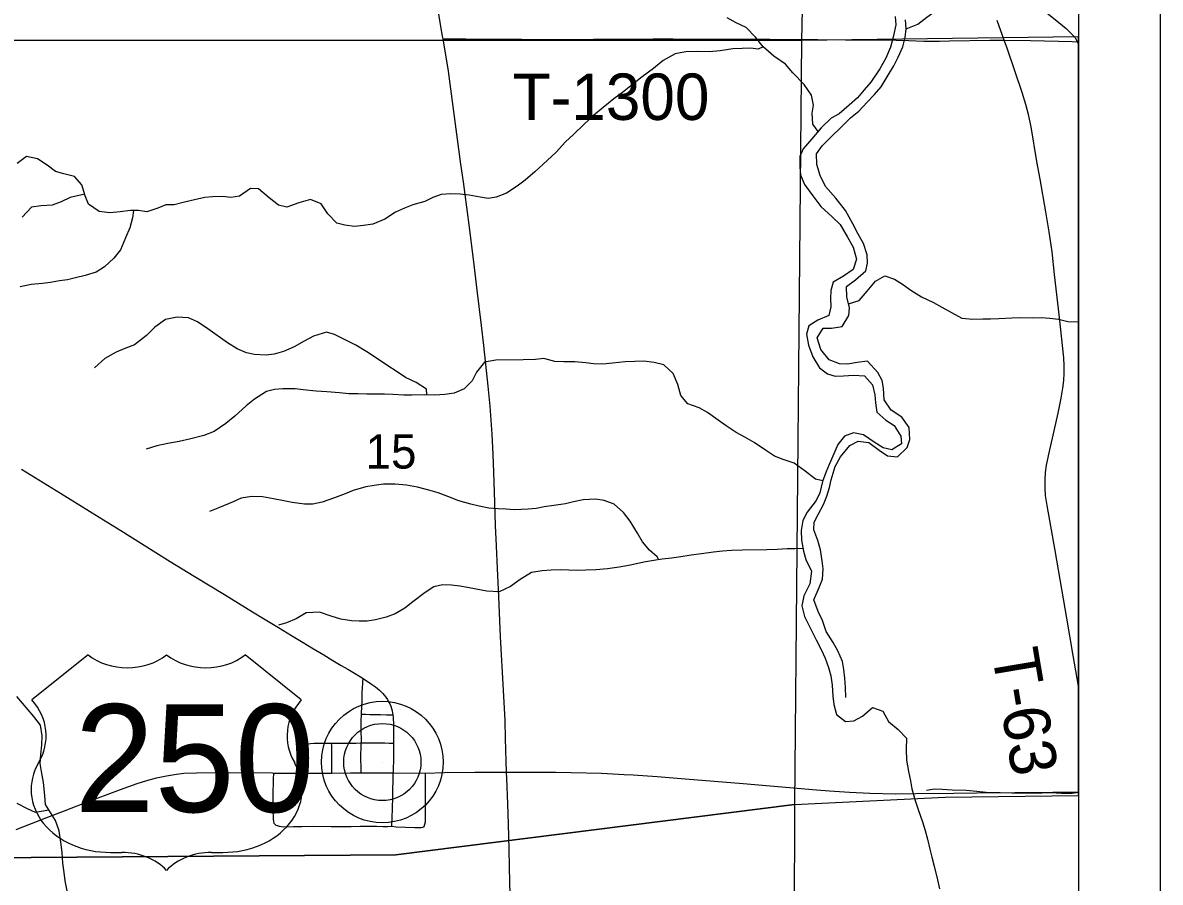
# Model space of a CAD drawing. Extents: x 0 to 34, y 0 to 22.
# Drawn here: x 14.616 to 16.008, y 10.238 to 11.289 of the extents above; entities that cross this region are included whole.
import ezdxf

# ---------------------------------------------------------------- set-up
doc = ezdxf.new("R2010")
doc.units = 0
for name, color, linetype in [('Default', 7, 'Continuous'), ('GM_X_County_Road', 7, 'Continuous'), ('GM_X_Major_River', 7, 'Continuous'), ('GM_X_Minor_River', 7, 'Continuous'), ('GM_X_Section', 7, 'Continuous'), ('GM_X_Section_Text', 7, 'Continuous'), ('GM_X_Township_Road', 7, 'Continuous'), ('GM_X_Township_Road_Text', 7, 'Continuous'), ('GM_X_Unincorporated', 7, 'Continuous'), ('GM_X_Unincorporated_Location', 7, 'Continuous'), ('GM_X_US_Location', 7, 'Continuous'), ('GM_X_US_Route', 7, 'Continuous'), ('GM_X_US_Shield', 7, 'Continuous'), ('SH_Data', 7, 'Continuous')]:
    doc.layers.add(name, color=color, linetype=linetype)

msp = doc.modelspace()

# ---------------------------------------------------------------- linework, layer by layer
at = {"layer": 'Default'}
msp.add_lwpolyline([(15.9079, 10.3439), (15.9079, 11.2722), (15.569, 11.2675), (15.5602, 10.3325), (15.7447, 10.3415)], close=True, dxfattribs=at)
at = {"layer": 'GM_X_County_Road'}
for points in [[(15.1304, 11.2698), (15.1298, 11.2729), (15.1239, 11.3066)], [(15.208, 10.3722), (15.2076, 10.3857), (15.2069, 10.4136), (15.2061, 10.4354), (15.2041, 10.4726), (15.2007, 10.5377), (15.1984, 10.5873), (15.1969, 10.6215), (15.1956, 10.6494), (15.1944, 10.6742), (15.1935, 10.7021), (15.1923, 10.7394), (15.1915, 10.7611), (15.1902, 10.786), (15.1878, 10.8201), (15.1856, 10.8448), (15.1801, 10.8942), (15.1773, 10.9189), (15.172, 10.9621), (15.1688, 10.9898), (15.1629, 11.0361), (15.1592, 11.0638), (15.1551, 11.0946), (15.1521, 11.1161), (15.1472, 11.153), (15.1427, 11.1869), (15.1368, 11.23), (15.1304, 11.2698)], [(14.6144, 10.7431), (14.6356, 10.7301), (14.662, 10.7138), (14.6858, 10.6991), (14.7096, 10.6844), (14.7359, 10.668), (14.7754, 10.6431), (14.7965, 10.63), (14.8256, 10.6121), (14.8627, 10.5895), (14.8972, 10.5685), (14.9105, 10.5605), (14.9291, 10.5493), (14.9449, 10.5395), (14.9591, 10.5308), (14.9698, 10.5243), (14.9844, 10.5157), (14.9953, 10.5091), (15.0056, 10.5029), (15.0137, 10.4982), (15.0239, 10.4921), (15.0327, 10.4867)], [(15.0327, 10.4867), (15.0428, 10.4799), (15.0476, 10.4765), (15.0524, 10.4725), (15.0566, 10.4685), (15.0602, 10.4642), (15.0622, 10.461), (15.0637, 10.4584), (15.065, 10.4557), (15.0662, 10.4529), (15.0671, 10.4501), (15.0679, 10.4472), (15.0685, 10.4447), (15.0689, 10.4425)], [(15.0689, 10.4425), (15.0694, 10.439), (15.0695, 10.4304), (15.0697, 10.4172), (15.0698, 10.4079)], [(15.0698, 10.4079), (15.0697, 10.3976), (15.0696, 10.3928), (15.0695, 10.3851), (15.0694, 10.3783), (15.0692, 10.3715)], [(15.2124, 10.2213), (15.2116, 10.2561), (15.2111, 10.2779), (15.2103, 10.3087), (15.2097, 10.3336), (15.2083, 10.3646), (15.208, 10.3722)]]:
    msp.add_lwpolyline(points, dxfattribs=at)
at = {"layer": 'GM_X_Major_River'}
for points in [[(15.6837, 11.2969), (15.6845, 11.2867), (15.6811, 11.2719), (15.6778, 11.2594), (15.6721, 11.2461), (15.6646, 11.2328), (15.6536, 11.2168), (15.6457, 11.2073), (15.6374, 11.1974), (15.6271, 11.1883), (15.615, 11.178), (15.6052, 11.1726), (15.5931, 11.1608), (15.5814, 11.1471), (15.5708, 11.135), (15.567, 11.1255), (15.5667, 11.1126), (15.5678, 11.1031), (15.5724, 11.0913), (15.5827, 11.0777), (15.5926, 11.0644), (15.6063, 11.052), (15.6162, 11.0425), (15.625, 11.027), (15.6322, 11.0149), (15.6364, 11.0001), (15.6323, 10.9872), (15.6202, 10.9792), (15.6077, 10.9719), (15.6047, 10.9617), (15.6043, 10.9518), (15.6047, 10.9419), (15.6025, 10.9309), (15.5888, 10.9252), (15.5779, 10.9183), (15.5752, 10.9084), (15.5776, 10.8948), (15.5829, 10.8804), (15.5909, 10.8671), (15.6008, 10.8596), (15.6103, 10.857), (15.6205, 10.8574), (15.6327, 10.8582), (15.6459, 10.8571), (15.6558, 10.8461), (15.6585, 10.834), (15.6593, 10.8241), (15.6609, 10.8127), (15.6723, 10.8029), (15.6822, 10.7965), (15.6905, 10.7836), (15.6913, 10.7741), (15.6796, 10.7669), (15.669, 10.7691), (15.6579, 10.7759), (15.6446, 10.785), (15.6325, 10.7876), (15.6215, 10.7834), (15.6132, 10.7731), (15.6072, 10.759), (15.6026, 10.7488), (15.5985, 10.7389), (15.5947, 10.7279), (15.5914, 10.7142), (15.5868, 10.7047), (15.5759, 10.6903), (15.5706, 10.6804), (15.5687, 10.6679), (15.5691, 10.6561), (15.5715, 10.6428), (15.5741, 10.6326), (15.581, 10.6182), (15.5792, 10.6026), (15.5716, 10.5882), (15.5694, 10.5757), (15.5724, 10.5628), (15.5786, 10.5507), (15.5869, 10.5344), (15.5934, 10.5215), (15.598, 10.5116), (15.6018, 10.5003), (15.6049, 10.49)], [(15.6232, 10.4635), (15.6228, 10.476), (15.622, 10.4874), (15.6208, 10.4977), (15.6189, 10.5075), (15.6135, 10.5208), (15.6078, 10.531), (15.5991, 10.5443), (15.5948, 10.5579), (15.5895, 10.5689), (15.5838, 10.5833), (15.5906, 10.5981), (15.5947, 10.6084), (15.5954, 10.6209), (15.5943, 10.6308), (15.5923, 10.6444), (15.5889, 10.6558), (15.5839, 10.6687), (15.5843, 10.6782), (15.5899, 10.6884), (15.5959, 10.6998), (15.6001, 10.7101), (15.6031, 10.7207), (15.6053, 10.7302), (15.6102, 10.7465), (15.6166, 10.7583), (15.628, 10.772), (15.6382, 10.7774), (15.6511, 10.7755), (15.664, 10.7664), (15.6743, 10.7593), (15.6864, 10.7582), (15.6982, 10.7696), (15.7015, 10.7794), (15.7007, 10.7939), (15.6916, 10.8067), (15.6787, 10.8154), (15.6699, 10.8279), (15.6691, 10.842), (15.6676, 10.8514), (15.6622, 10.8613), (15.6497, 10.8753), (15.6372, 10.8734), (15.6254, 10.8714), (15.6156, 10.8718), (15.6026, 10.8767), (15.5927, 10.8895), (15.5881, 10.9036), (15.5953, 10.9157), (15.6056, 10.9154), (15.6185, 10.9177), (15.6268, 10.931), (15.6275, 10.9405), (15.6244, 10.9538), (15.624, 10.9666), (15.635, 10.9747), (15.6475, 10.9857), (15.6497, 10.9952), (15.6493, 11.0054), (15.6447, 11.0191), (15.6378, 11.0316), (15.6317, 11.0433), (15.6226, 11.0596), (15.6108, 11.0747), (15.5982, 11.0888), (15.5917, 11.1024), (15.5875, 11.116), (15.5871, 11.1289), (15.5943, 11.1388), (15.6056, 11.1502), (15.617, 11.1613), (15.6287, 11.1731), (15.6389, 11.1811), (15.6491, 11.1921), (15.6582, 11.2016), (15.6662, 11.2111), (15.6748, 11.2252), (15.682, 11.2366), (15.6873, 11.2472), (15.6929, 11.2598), (15.6959, 11.2712), (15.6971, 11.2818), (15.6963, 11.2928)], [(15.6049, 10.49), (15.6065, 10.4786), (15.6073, 10.4654), (15.6084, 10.4551), (15.6119, 10.443), (15.6229, 10.4343), (15.6331, 10.4351), (15.6434, 10.4408), (15.6558, 10.4515), (15.6684, 10.447), (15.6752, 10.4341), (15.6874, 10.4246), (15.6973, 10.4137), (15.697, 10.4004), (15.6974, 10.3871), (15.6997, 10.3731), (15.7024, 10.3617), (15.7039, 10.3518), (15.7078, 10.3374), (15.712, 10.3253), (15.7169, 10.3113), (15.7204, 10.301), (15.7231, 10.2904), (15.7261, 10.2779), (15.7285, 10.2684), (15.7311, 10.2574), (15.7354, 10.2404), (15.7377, 10.2294)]]:
    msp.add_lwpolyline(points, dxfattribs=at)
at = {"layer": 'GM_X_Minor_River'}
for points in [[(15.697, 11.2817), (15.7111, 11.2875), (15.7224, 11.2963), (15.7342, 11.3047), (15.7501, 11.3142), (15.7641, 11.3203), (15.7758, 11.3238), (15.7857, 11.3265), (15.7952, 11.3261), (15.8077, 11.3246), (15.8233, 11.3213), (15.8335, 11.3183), (15.8517, 11.3123), (15.8635, 11.3058), (15.8795, 11.2934), (15.8928, 11.2824), (15.9038, 11.2711), (15.9079, 11.2629)], [(15.5892, 11.1563), (15.5828, 11.1653), (15.582, 11.1786), (15.5835, 11.1885), (15.5812, 11.2006), (15.5721, 11.2139), (15.5584, 11.2279), (15.5492, 11.2385), (15.5352, 11.2483), (15.5222, 11.26), (15.5127, 11.2718), (15.5013, 11.2835), (15.4888, 11.2891), (15.4778, 11.2952)], [(15.5222, 11.26), (15.5158, 11.257), (15.5063, 11.2581), (15.4961, 11.258), (15.4847, 11.2573), (15.4695, 11.2549), (15.4559, 11.2538), (15.4415, 11.2541), (15.4274, 11.2537), (15.4142, 11.2513), (15.3998, 11.2433), (15.388, 11.2334), (15.374, 11.2231), (15.3623, 11.2136), (15.3498, 11.2041), (15.3392, 11.1961), (15.3263, 11.1858), (15.3142, 11.1759), (15.3029, 11.1653), (15.29, 11.1527), (15.2802, 11.1436), (15.2685, 11.131), (15.2575, 11.1207), (15.2424, 11.107), (15.2306, 11.0967), (15.2208, 11.0895), (15.2079, 11.0807), (15.1954, 11.0758), (15.1856, 11.0742), (15.1757, 11.0757), (15.1624, 11.0783), (15.1514, 11.0794), (15.14, 11.0801), (15.1279, 11.079), (15.1177, 11.0755), (15.1078, 11.0706), (15.0934, 11.0667), (15.0832, 11.0625), (15.0722, 11.0575), (15.0589, 11.0488), (15.0445, 11.0427), (15.0328, 11.0411), (15.0218, 11.0399), (15.01, 11.0418), (15.0005, 11.0441), (14.9891, 11.0554), (14.9811, 11.0679), (14.9682, 11.0732), (14.9538, 11.0689), (14.939, 11.0636), (14.9291, 11.0662), (14.9174, 11.0749), (14.9044, 11.0859), (14.8946, 11.0866), (14.8813, 11.0771), (14.8707, 11.0755), (14.8608, 11.0766), (14.8483, 11.0762), (14.8388, 11.0754), (14.8263, 11.0727), (14.8138, 11.0697), (14.8013, 11.0666), (14.7911, 11.0666), (14.7812, 11.0624), (14.768, 11.0578), (14.7577, 11.0596), (14.7478, 11.0596), (14.735, 11.058), (14.7224, 11.0569), (14.7095, 11.0583), (14.6966, 11.0674), (14.6924, 11.0776), (14.6882, 11.0909), (14.6791, 11.1011), (14.6662, 11.1045), (14.6559, 11.1075), (14.646, 11.1151), (14.6342, 11.123), (14.6206, 11.1256), (14.6092, 11.1172)], [(14.6919, 11.0794), (14.6738, 11.0753), (14.6628, 11.07), (14.6519, 11.0661), (14.6386, 11.0653), (14.6268, 11.0638), (14.6151, 11.0516)], [(14.7516, 11.0596), (14.7501, 11.0505), (14.7468, 11.0383), (14.7419, 11.0262), (14.7355, 11.0114), (14.7275, 11.0011), (14.7158, 10.9908), (14.7056, 10.9843), (14.6923, 10.9801), (14.6806, 10.9771), (14.6707, 10.9747), (14.6608, 10.9736), (14.6499, 10.9716), (14.64, 10.9701), (14.6263, 10.9689), (14.6127, 10.9662)], [(15.6264, 10.9453), (15.6396, 10.9496), (15.6494, 10.961), (15.6593, 10.9732), (15.671, 10.9797), (15.6828, 10.9756), (15.6926, 10.9695), (15.7025, 10.9623), (15.7158, 10.954), (15.7303, 10.9469), (15.7405, 10.9412), (15.7523, 10.9348), (15.7652, 10.928), (15.7785, 10.9265), (15.7906, 10.9269), (15.8001, 10.927), (15.8104, 10.9274), (15.8263, 10.9282), (15.8358, 10.9286), (15.8513, 10.9283), (15.8623, 10.9287), (15.8726, 10.9279), (15.8832, 10.9265), (15.895, 10.9238), (15.9079, 10.9232)], [(15.1106, 10.8341), (15.11, 10.841), (15.0974, 10.8493), (15.0845, 10.8553), (15.0728, 10.8629), (15.0629, 10.8693), (15.0488, 10.8788), (15.037, 10.8867), (15.0237, 10.8946), (15.0104, 10.9014), (14.9975, 10.9078), (14.9876, 10.9108), (14.9717, 10.9058), (14.9604, 10.8997), (14.9479, 10.8929), (14.935, 10.8871), (14.9236, 10.8837), (14.9138, 10.8825), (14.8997, 10.8832), (14.8898, 10.8855), (14.8785, 10.8904), (14.8667, 10.8976), (14.8423, 10.9149), (14.8298, 10.9232), (14.8188, 10.9281), (14.8051, 10.9292), (14.7907, 10.9262), (14.7775, 10.917), (14.7673, 10.9067), (14.7529, 10.8953), (14.7408, 10.8907), (14.7301, 10.8861), (14.7165, 10.8785), (14.7036, 10.8671)], [(15.5951, 10.7289), (15.586, 10.7309), (15.5734, 10.7404), (15.5598, 10.7502), (15.5465, 10.7547), (15.5358, 10.7588), (15.5248, 10.7664), (15.5111, 10.7755), (15.4994, 10.7822), (15.4891, 10.7879), (15.4766, 10.7962), (15.4671, 10.803), (15.4537, 10.8125), (15.4435, 10.8181), (15.4298, 10.823), (15.4211, 10.8332), (15.4176, 10.8465), (15.4119, 10.8601), (15.4005, 10.8707), (15.3887, 10.8734), (15.3758, 10.8752), (15.3648, 10.8748), (15.353, 10.8744), (15.3375, 10.8728), (15.3257, 10.8716), (15.3144, 10.872), (15.3049, 10.8731), (15.2916, 10.8742), (15.2779, 10.8745), (15.2669, 10.8749), (15.2536, 10.8786), (15.2434, 10.8771), (15.2282, 10.8767), (15.1949, 10.8766), (15.1812, 10.8739), (15.1714, 10.8617), (15.1661, 10.851), (15.1563, 10.8415), (15.1438, 10.8362), (15.1324, 10.8346), (15.1203, 10.8338), (15.1081, 10.8342), (15.0922, 10.8337), (15.0823, 10.8337), (15.0687, 10.8344), (15.0588, 10.8348), (15.0372, 10.8347), (15.0266, 10.8351), (15.0148, 10.8354), (15.0034, 10.8365), (14.9882, 10.8376), (14.975, 10.8387), (14.959, 10.8402), (14.9492, 10.8413), (14.9344, 10.8412), (14.9241, 10.8404), (14.9143, 10.8381), (14.8995, 10.8286), (14.8893, 10.8206), (14.8753, 10.808), (14.8643, 10.7989), (14.8503, 10.789), (14.8374, 10.7844), (14.8215, 10.7802), (14.8075, 10.7771), (14.7934, 10.7744), (14.7802, 10.7717), (14.7669, 10.7675)], [(15.3944, 10.6322), (15.3924, 10.6358), (15.3829, 10.6438), (15.3742, 10.654), (15.3681, 10.6646), (15.3593, 10.6794), (15.3509, 10.69), (15.3395, 10.7002), (15.3274, 10.7047), (15.3171, 10.7062), (15.3019, 10.7054), (15.2898, 10.7031), (15.28, 10.7008), (15.2659, 10.6984), (15.2542, 10.6969), (15.2443, 10.695), (15.2345, 10.6942), (15.2174, 10.6934), (15.2075, 10.6941), (15.1977, 10.6944), (15.1863, 10.6955), (15.1745, 10.6978), (15.1643, 10.7004), (15.1495, 10.7042), (15.1362, 10.7094), (15.1244, 10.7139), (15.113, 10.7173), (15.099, 10.7211), (15.0857, 10.7233), (15.0716, 10.7248), (15.0576, 10.7247), (15.0458, 10.7232), (15.0356, 10.7216), (15.0204, 10.717), (15.0106, 10.7128), (14.9973, 10.7079), (14.9822, 10.7025), (14.9708, 10.7002), (14.9606, 10.7002), (14.9458, 10.7024), (14.9336, 10.7046), (14.923, 10.7069), (14.9093, 10.7091), (14.8964, 10.7098), (14.8832, 10.7075), (14.8733, 10.7029), (14.8566, 10.696), (14.8445, 10.6911)], [(15.5709, 10.6458), (15.5608, 10.6455), (15.5513, 10.6454), (15.5392, 10.6446), (15.5263, 10.6442), (15.4967, 10.6441), (15.4831, 10.6437), (15.4721, 10.6429), (15.4611, 10.6414), (15.4467, 10.6394), (15.4338, 10.6379), (15.4213, 10.6359), (15.4099, 10.634), (15.3985, 10.6328), (15.3883, 10.6313), (15.3758, 10.6293), (15.3595, 10.6255), (15.3458, 10.6232), (15.3314, 10.6212), (15.3174, 10.6197), (15.3049, 10.6193), (15.2942, 10.6192), (15.284, 10.6196), (15.2745, 10.6199), (15.2624, 10.6195), (15.2517, 10.6187), (15.2385, 10.6164), (15.2245, 10.608), (15.2127, 10.5996), (15.1991, 10.5931), (15.1839, 10.5938), (15.1706, 10.5961), (15.1604, 10.5983), (15.1509, 10.5998), (15.1407, 10.6009), (15.1297, 10.6016), (15.119, 10.599), (15.1084, 10.5921), (15.0933, 10.5807), (15.0835, 10.573), (15.0717, 10.5662), (15.0607, 10.562), (15.0475, 10.5585), (15.0376, 10.557), (15.0277, 10.5569), (15.0183, 10.5573), (15.005, 10.5595), (14.9932, 10.5633), (14.9792, 10.5682), (14.9628, 10.5674), (14.9504, 10.5597), (14.9386, 10.5548), (14.9291, 10.5521)], [(14.6702, 10.2269), (14.6679, 10.2394), (14.6668, 10.2493), (14.6652, 10.261), (14.664, 10.2739), (14.6625, 10.2864), (14.6605, 10.3005), (14.6559, 10.313), (14.6438, 10.3327), (14.643, 10.3437), (14.6414, 10.3596), (14.6391, 10.3729), (14.6372, 10.3827), (14.6379, 10.3937), (14.6394, 10.4051), (14.6397, 10.4169), (14.6378, 10.4298), (14.6294, 10.4404), (14.6086, 10.4647)], [(15.722, 10.3501), (15.7316, 10.3519), (15.7411, 10.3516), (15.7532, 10.3508), (15.7703, 10.3501), (15.7836, 10.349), (15.7988, 10.3472), (15.8121, 10.3472), (15.8261, 10.3469), (15.8636, 10.347), (15.8739, 10.3474), (15.8872, 10.3467), (15.9001, 10.3467), (15.9079, 10.3476)], [(14.648, 10.3259), (14.6316, 10.3228), (14.6218, 10.3273), (14.6092, 10.3341)]]:
    msp.add_lwpolyline(points, dxfattribs=at)
at = {"layer": 'GM_X_Section'}
for points in [[(15.5907, 12.2877), (15.569, 11.2675), (14.5738, 11.2682), (14.5977, 12.2808), (15.0525, 12.2941)], [(14.5738, 11.2682), (15.569, 11.2675), (15.5602, 10.3325), (15.0726, 10.2709), (14.5701, 10.2676)], [(14.5701, 10.2676), (15.0726, 10.2709), (15.5602, 10.3325), (15.5576, 9.3334), (15.0625, 9.2635), (14.5716, 9.2663)]]:
    msp.add_lwpolyline(points, close=True, dxfattribs=at)
at = {"layer": 'GM_X_Township_Road'}
for points in [[(15.8169, 11.268), (15.8085, 11.2921)], [(15.1304, 11.2698), (15.1364, 11.2698), (15.1487, 11.2697), (15.1579, 11.2695), (15.1766, 11.2693), (15.2045, 11.2691), (15.2262, 11.2692), (15.2542, 11.2689), (15.2906, 11.269), (15.3144, 11.2693), (15.3381, 11.2694), (15.3873, 11.2695), (15.412, 11.2695), (15.4312, 11.2694), (15.4549, 11.2694), (15.4925, 11.2691), (15.53, 11.2691), (15.5639, 11.269), (15.5888, 11.2687), (15.6229, 11.2684), (15.6849, 11.268), (15.7004, 11.2678), (15.7188, 11.267), (15.7376, 11.267), (15.7501, 11.2673), (15.7992, 11.2679), (15.8169, 11.268)], [(15.9079, 10.4775), (15.9014, 10.5149), (15.8935, 10.5608), (15.8794, 10.6435), (15.8695, 10.6985), (15.8676, 10.7108), (15.8669, 10.7202), (15.8669, 10.7297), (15.8674, 10.7388), (15.8688, 10.7481), (15.8718, 10.7629), (15.8831, 10.8116), (15.8867, 10.8299), (15.8887, 10.8422), (15.8899, 10.8514), (15.8904, 10.8607), (15.8904, 10.87), (15.8898, 10.8793), (15.8846, 10.9287), (15.8786, 10.9811), (15.8756, 11.009), (15.8719, 11.0336), (15.868, 11.0581), (15.8608, 11.098), (15.857, 11.1194), (15.8498, 11.1621), (15.8465, 11.1772), (15.8435, 11.1893), (15.839, 11.2041), (15.83, 11.2306), (15.8209, 11.257), (15.8169, 11.268)], [(15.8169, 11.268), (15.8491, 11.2678), (15.8834, 11.2669), (15.9, 11.2662), (15.9079, 11.2658)], [(15.0305, 10.4432), (15.031, 10.4533), (15.0311, 10.4588), (15.0313, 10.4676), (15.0317, 10.4769), (15.032, 10.4792), (15.0323, 10.4824), (15.0327, 10.4867)], [(15.0302, 10.4082), (15.0303, 10.4092), (15.0301, 10.4247), (15.0302, 10.4347), (15.0305, 10.4432)], [(15.0305, 10.4432), (15.0353, 10.4431), (15.0406, 10.443), (15.0474, 10.4429), (15.0536, 10.4428), (15.0609, 10.4426), (15.0689, 10.4425)], [(14.959, 10.3711), (14.959, 10.376), (14.959, 10.3791), (14.959, 10.3835), (14.9589, 10.3882), (14.9591, 10.3937), (14.9595, 10.3979), (14.9598, 10.4009), (14.9607, 10.4034), (14.962, 10.4051)], [(14.962, 10.4051), (14.9635, 10.406), (14.9652, 10.4069), (14.9682, 10.4073), (14.972, 10.4076), (14.9763, 10.4077), (14.9939, 10.4078)], [(14.9939, 10.4078), (15.007, 10.4078), (15.0172, 10.4077), (15.024, 10.4079), (15.0302, 10.4082)], [(14.994, 10.371), (14.9941, 10.3758), (14.994, 10.3798), (14.994, 10.3838), (14.9941, 10.3871), (14.9943, 10.3952), (14.994, 10.4044), (14.9939, 10.4078)], [(15.03, 10.3715), (15.0299, 10.3788), (15.0297, 10.3878), (15.0302, 10.4082)], [(15.0302, 10.4082), (15.0364, 10.4082), (15.0498, 10.408), (15.0591, 10.408), (15.0644, 10.4079), (15.0698, 10.4079)], [(14.9257, 10.3074), (14.9237, 10.3096), (14.9231, 10.3118), (14.9229, 10.3148), (14.9225, 10.3271), (14.9224, 10.3364), (14.9225, 10.346), (14.9227, 10.3608), (14.9228, 10.3637), (14.9231, 10.3712)], [(15.0677, 10.3063), (15.0682, 10.3164), (15.0685, 10.3277), (15.0689, 10.3415), (15.0692, 10.3715)], [(15.1071, 10.3059), (15.1081, 10.3086), (15.1088, 10.3115), (15.109, 10.3235), (15.1089, 10.3332), (15.1087, 10.3441), (15.1088, 10.3538), (15.1088, 10.3648), (15.1089, 10.3711)], [(14.9257, 10.3074), (14.9274, 10.3068), (14.9296, 10.3061), (14.9321, 10.3056), (14.9355, 10.3055), (14.9472, 10.3057), (14.9573, 10.3059), (14.9716, 10.306), (14.9935, 10.3058), (15.0057, 10.3057), (15.0179, 10.3058), (15.0289, 10.3061), (15.0396, 10.3061), (15.049, 10.306), (15.0569, 10.3056), (15.0622, 10.3058), (15.0677, 10.3063)], [(15.0677, 10.3063), (15.073, 10.3054), (15.0957, 10.3044), (15.1033, 10.3044), (15.1054, 10.3048), (15.1071, 10.3059)]]:
    msp.add_lwpolyline(points, dxfattribs=at)
at = {"layer": 'GM_X_Unincorporated'}
for radius in [0.0744, 0.0472]:
    msp.add_circle((15.056, 10.3846), radius, dxfattribs=at)
at = {"layer": 'GM_X_Unincorporated_Location'}
msp.add_line((15.056, 10.3846), (15.056, 10.3846), dxfattribs=at)
at = {"layer": 'GM_X_US_Route'}
for points in [[(14.608, 10.3019), (14.6455, 10.3168), (14.6658, 10.3247), (14.6919, 10.3347), (14.7354, 10.3511), (14.7559, 10.3584), (14.7677, 10.3621), (14.7796, 10.3653), (14.7917, 10.3678), (14.804, 10.3699), (14.8132, 10.371), (14.8286, 10.3715), (14.869, 10.3717), (14.9217, 10.3713), (14.9231, 10.3712)], [(14.9231, 10.3712), (14.9403, 10.371), (14.959, 10.3711), (14.994, 10.371), (15.0172, 10.3715), (15.03, 10.3715), (15.0607, 10.3714), (15.0692, 10.3715), (15.1089, 10.3711), (15.1321, 10.3718), (15.1693, 10.3723), (15.2034, 10.3722), (15.208, 10.3722)], [(15.208, 10.3722), (15.2623, 10.3723), (15.2682, 10.3722)], [(15.2682, 10.3722), (15.287, 10.372), (15.3242, 10.3709), (15.3521, 10.3696), (15.3629, 10.3689), (15.3924, 10.3669), (15.4265, 10.364), (15.4977, 10.3583), (15.5871, 10.3508)], [(15.5871, 10.3508), (15.603, 10.3495), (15.6278, 10.3477), (15.6527, 10.3466), (15.6838, 10.3459), (15.7087, 10.346), (15.7553, 10.3465), (15.7833, 10.3469), (15.8299, 10.3472), (15.8765, 10.3479), (15.9076, 10.3481), (15.9079, 10.3481)]]:
    msp.add_lwpolyline(points, dxfattribs=at)
at = {"layer": 'GM_X_US_Shield'}
for p, q in [((14.6959, 10.5158), (14.6272, 10.4608)), ((14.9568, 10.4608), (14.8881, 10.5158)), ((14.7233, 10.2741), (14.7371, 10.2741)), ((14.8469, 10.2741), (14.8607, 10.2741))]:
    msp.add_line(p, q, dxfattribs=at)
for centre, major_axis, start_param, end_param in [((14.7439, 10.555), (-0.0687, 0), 0.795399, 2.346194), ((14.8401, 10.555), (-0.0687, 0), 0.795399, 2.346194), ((14.5485, 10.4167), (0.0961, 0), 5.838949, 6.894067), ((15.0355, 10.4167), (-0.0961, 0), 5.672304, 6.727422), ((14.7223, 10.351), (0.0961, 0), 2.702327, 4.723529), ((14.8617, 10.351), (-0.0961, 0), 1.559657, 3.580859), ((14.7371, 10.2191), (-0.0687, 0), 3.785094, 4.712389), ((14.8469, 10.2191), (-0.0687, 0), 4.712389, 5.639684)]:
    msp.add_ellipse(centre, major_axis=major_axis, ratio=0.8, start_param=start_param, end_param=end_param, dxfattribs=at)
at = {"layer": 'SH_Data'}
for p, q in [((16.0079, 16.0775), (16.0079, 9.0775)), ((15.9079, 15.9775), (15.9079, 9.1775))]:
    msp.add_line(p, q, dxfattribs=at)

# ---------------------------------------------------------------- texts
at = {"layer": 'GM_X_Section_Text'}
msp.add_text('15', height=0.04186, rotation=0, dxfattribs=at).set_placement((15.0355, 10.7438))
at = {"layer": 'GM_X_Township_Road_Text'}
for s, rotation, p in [('T-1300', 0, (15.2155, 11.1704)), ('T-63', 279.5788, (15.8015, 10.5189))]:
    msp.add_text(s, height=0.05682, rotation=rotation, dxfattribs=at).set_placement(p)
at = {"layer": 'GM_X_US_Location'}
for s in ['0', '/']:
    msp.add_text(s, height=0.000189, dxfattribs=at).set_placement((14.7921, 10.3893))
msp.add_text('250', height=0.000189, rotation=0, dxfattribs=at).set_placement((14.7338, 10.3501))
at = {"layer": 'GM_X_US_Shield'}
msp.add_text('250', height=0.13184, dxfattribs=at).set_placement((14.6792, 10.3235))

doc.saveas('drawing.dxf')
